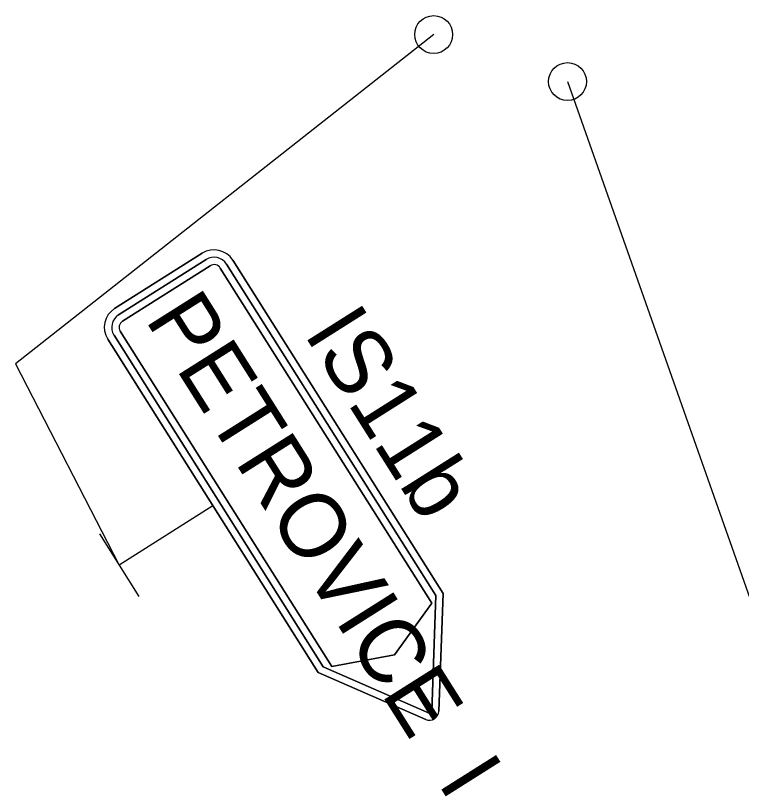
# Model space of a CAD drawing. Extents: x -688893 to -679983, y -1088371 to -1075771.
# Drawn here: x -683817 to -683228, y -1077442 to -1076809 of the extents above; entities that cross this region are included whole.
import ezdxf

# ---------------------------------------------------------------- set-up
doc = ezdxf.new("R2010")
doc.units = 0
for name, color, linetype in [('SDZ', 7, 'Continuous'), ('SDZ ozn', 7, 'Continuous'), ('SDZ plochy', 7, 'Continuous'), ('SDZ symbol', 7, 'Continuous')]:
    doc.layers.add(name, color=color, linetype=linetype)

msp = doc.modelspace()

# ---------------------------------------------------------------- linework, layer by layer
at = {"layer": 'SDZ'}
for p, q in [((-683736.94, -1077046.62), (-683665.92, -1077001.77)), ((-683662.72, -1077006.84), (-683733.74, -1077051.7)), ((-683641.09, -1077007.37), (-683470.31, -1077277.75)), ((-683730.53, -1077056.77), (-683659.51, -1077011.91)), ((-683651.24, -1077013.78), (-683479.5, -1077285.68)), ((-683476.34, -1077279.44), (-683646.16, -1077010.58)), ((-683560.66, -1077336.95), (-683732.4, -1077065.05)), ((-683571.77, -1077341.84), (-683742.55, -1077071.46)), ((-683737.47, -1077068.25), (-683567.66, -1077337.11)), ((-683657.16, -1077206.65), (-683733.25, -1077254.71)), ((-683749.27, -1077229.34), (-683717.23, -1077280.07)), ((-683479.67, -1077373.54), (-683476.34, -1077279.44)), ((-683470.31, -1077277.75), (-683474, -1077373.25)), ((-683479.5, -1077285.68), (-683509.82, -1077327.55)), ((-683509.82, -1077327.55), (-683560.66, -1077336.95)), ((-683567.66, -1077337.11), (-683481.77, -1077374.86)), ((-683484.49, -1077379.84), (-683571.77, -1077341.84)), ((-683473.99, -1077373.05), (-683473.99, -1077373.05))]:
    msp.add_line(p, q, dxfattribs=at)
for points in [[(-683478.12, -1076824.35), (-683817.29, -1077091.35), (-683733.25, -1077254.71)], [(-683369.54, -1076862.48), (-683181.11, -1077396.48), (-682974.49, -1077387.14)], [(-683369.54, -1076862.48), (-683181.11, -1077396.48), (-682974.49, -1077387.14)]]:
    msp.add_lwpolyline(points, dxfattribs=at)
for centre in [(-683478.12, -1076824.35), (-683369.54, -1076862.48), (-683369.54, -1076862.48)]:
    msp.add_circle(centre, 15.36, dxfattribs=at)
for centre, radius, start, end in [((-683656.31, -1077016.98), 18, 32.27762, 122.27762), ((-683656.31, -1077016.98), 12, 32.27762, 122.27762), ((-683656.31, -1077016.98), 6, 32.27762, 122.27762), ((-683727.33, -1077061.84), 18, 122.27762, 212.27762), ((-683727.33, -1077061.84), 12, 122.27762, 212.27762), ((-683727.33, -1077061.84), 6, 122.27762, 212.27762), ((-683481.49, -1077372.97), 7.5, 246.46939, 357.78766), ((-683481.17, -1077373.48), 1.5, 246.27408, 357.97696)]:
    msp.add_arc(centre, radius, start, end, dxfattribs=at)
at = {"layer": 'SDZ plochy'}
for p, q in [((-683665.92, -1077001.77), (-683736.94, -1077046.62)), ((-683733.74, -1077051.7), (-683662.72, -1077006.84)), ((-683662.72, -1077006.84), (-683733.74, -1077051.7)), ((-683470.31, -1077277.75), (-683641.09, -1077007.37)), ((-683659.51, -1077011.91), (-683730.53, -1077056.77)), ((-683730.53, -1077056.77), (-683659.51, -1077011.91)), ((-683479.5, -1077285.68), (-683651.24, -1077013.78)), ((-683651.24, -1077013.78), (-683479.5, -1077285.68)), ((-683646.16, -1077010.58), (-683476.34, -1077279.44)), ((-683476.34, -1077279.44), (-683646.16, -1077010.58)), ((-683732.4, -1077065.05), (-683560.66, -1077336.95)), ((-683560.66, -1077336.95), (-683732.4, -1077065.05)), ((-683742.55, -1077071.46), (-683571.77, -1077341.84)), ((-683567.66, -1077337.11), (-683737.47, -1077068.25)), ((-683737.47, -1077068.25), (-683567.66, -1077337.11)), ((-683476.34, -1077279.44), (-683479.67, -1077373.54)), ((-683479.67, -1077373.54), (-683476.34, -1077279.44)), ((-683474, -1077373.25), (-683470.31, -1077277.75)), ((-683509.82, -1077327.55), (-683479.5, -1077285.68)), ((-683479.5, -1077285.68), (-683509.82, -1077327.55)), ((-683560.66, -1077336.95), (-683509.82, -1077327.55)), ((-683509.82, -1077327.55), (-683560.66, -1077336.95)), ((-683481.77, -1077374.86), (-683567.66, -1077337.11)), ((-683567.66, -1077337.11), (-683481.77, -1077374.86)), ((-683571.77, -1077341.84), (-683484.49, -1077379.84))]:
    msp.add_line(p, q, dxfattribs=at)
for centre, radius, start, end in [((-683656.31, -1077016.98), 18, 32.27762, 122.27762), ((-683656.31, -1077016.98), 12, 32.27762, 122.27762), ((-683656.31, -1077016.98), 12, 32.27762, 122.27762), ((-683656.31, -1077016.98), 6, 32.27762, 122.27762), ((-683656.31, -1077016.98), 6, 32.27762, 122.27762), ((-683727.33, -1077061.84), 18, 122.27762, 212.27762), ((-683727.33, -1077061.84), 12, 122.27762, 212.27762), ((-683727.33, -1077061.84), 12, 122.27762, 212.27762), ((-683727.33, -1077061.84), 6, 122.27762, 212.27762), ((-683727.33, -1077061.84), 6, 122.27762, 212.27762), ((-683481.49, -1077372.97), 7.5, 246.46939, 357.78766), ((-683481.17, -1077373.48), 1.5, 246.27408, 357.97696), ((-683481.17, -1077373.48), 1.5, 246.27408, 357.97696)]:
    msp.add_arc(centre, radius, start, end, dxfattribs=at)

# ---------------------------------------------------------------- texts
at = {"layer": 'SDZ ozn'}
msp.add_text('IS11b', height=52.5, rotation=302.27762, dxfattribs=at).set_placement((-683584.04, -1077066.89))
at = {"layer": 'SDZ symbol'}
msp.add_text('PETROVICE  I', height=52.5, rotation=302.27762, dxfattribs=at).set_placement((-683712.83, -1077055.31))

doc.saveas('drawing.dxf')
